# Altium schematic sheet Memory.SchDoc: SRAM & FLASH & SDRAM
size A4; DocumentNumber: MB1165; Revision: C.1; SheetNumber: 4; SheetTotal: 17; Project: STM32469I-EVAL
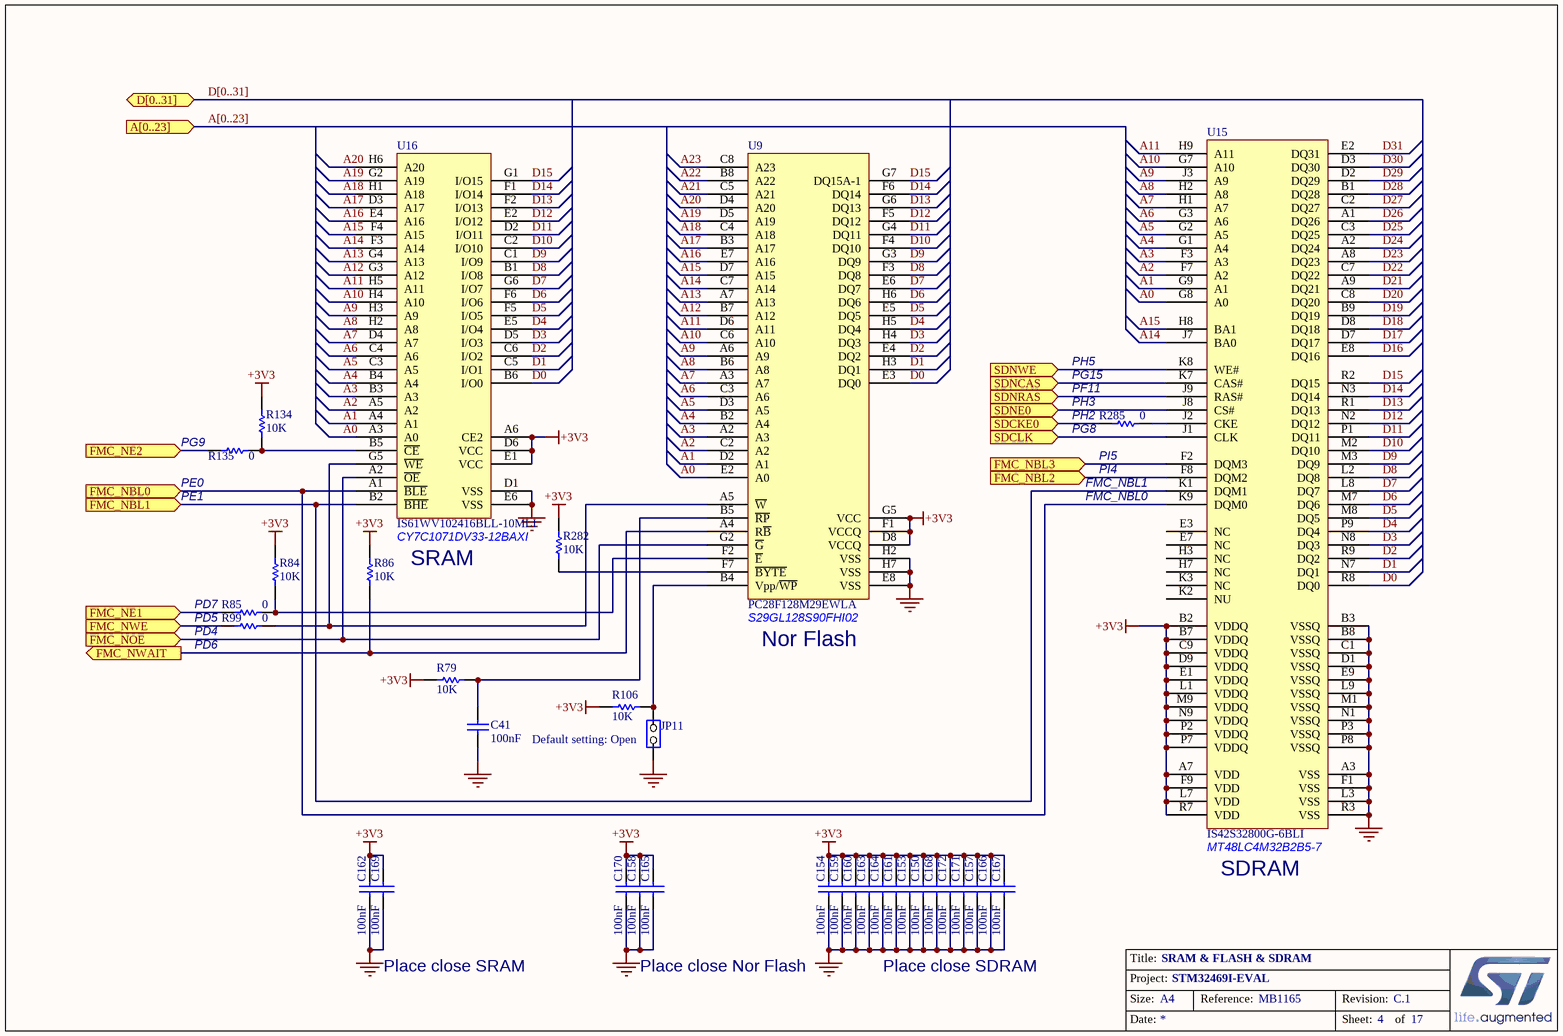
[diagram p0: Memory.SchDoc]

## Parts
C41  100nF  [0603C]
C150  100nF  [0603C]
C153  100nF  [0603C]
C154  100nF  [0603C]
C157  100nF  [0603C]
C158  100nF  [0603C]
C159  100nF  [0603C]
C160  100nF  [0603C]
C161  100nF  [0603C]
C162  100nF  [0603C]
C163  100nF  [0603C]
C164  100nF  [0603C]
C165  100nF  [0603C]
C166  100nF  [0603C]
C167  100nF  [0603C]
C168  100nF  [0603C]
C169  100nF  [0603C]
C170  100nF  [0603C]
C171  100nF  [0603C]
C172  100nF  [0603C]
JP11  (no value)  [SIP2]
R79  10K  [0603R]
R84  10K  [0603R]
R85  0  [0603R]
R86  10K  [0603R]
R99  0  [0603R]
R106  10K  [0603R]
R134  10K  [0603R]
R135  0  [0603R]
R282  10K  [0603R]
R285  0  [0603R]
U9  PC28F128M29EWLA  [FBGA64_1_11X13]
U15  IS42S32800G-6BLI  [FBGA90_0R8_8X13]
U16  IS61WV102416BLL-10MLI  [BGA48_0R75_9X11]

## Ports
A[0..23] (in), D[0..31] (bidir), FMC_NBL0 (in), FMC_NBL1 (in), FMC_NBL2 (in), FMC_NBL3 (in), FMC_NE1 (in), FMC_NE2 (in), FMC_NOE (in), FMC_NWAIT (out), FMC_NWE (in), SDCKE0 (in), SDCLK (in), SDNCAS (in), SDNE0 (in), SDNRAS (in), SDNWE (in)

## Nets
+3V3: C150.1 C153.1 C154.1 C157.1 C158.1 C159.1 C160.1 C161.1 C162.1 C163.1 C164.1 C165.1 C166.1 C167.1 C168.1 C169.1 C170.1 C171.1 C172.1 R79.1 R84.2 R86.2 R106.2 R134.2 R282.2 U9.D8(VCCQ) U9.F1(VCCQ) U9.G5(VCC) U15.A7(VDD) U15.B2(VDDQ) U15.B7(VDDQ) U15.C9(VDDQ) U15.D9(VDDQ) U15.E1(VDDQ) U15.F9(VDD) U15.L1(VDDQ) U15.L7(VDD) U15.M9(VDDQ) U15.N9(VDDQ) U15.P2(VDDQ) U15.P7(VDDQ) U15.R7(VDD) U16.A6(CE2) U16.D6(VCC) U16.E1(VCC)
GND: C41.2 C150.2 C153.2 C154.2 C157.2 C158.2 C159.2 C160.2 C161.2 C162.2 C163.2 C164.2 C165.2 C166.2 C167.2 C168.2 C169.2 C170.2 C171.2 C172.2 JP11.1(COMMON) U9.E8(VSS) U9.H2(VSS) U9.H7(VSS) U15.A3(VSS) U15.B3(VSSQ) U15.B8(VSSQ) U15.C1(VSSQ) U15.D1(VSSQ) U15.E9(VSSQ) U15.F1(VSS) U15.L3(VSS) U15.L9(VSSQ) U15.M1(VSSQ) U15.N1(VSSQ) U15.P3(VSSQ) U15.P8(VSSQ) U15.R3(VSS) U16.D1(VSS) U16.E6(VSS)
A0: U9.E2(A0) U15.G8(A0) U16.A3(A0)
A1: U9.D2(A1) U15.G9(A1) U16.A4(A1)
A2: U9.C2(A2) U15.F7(A2) U16.A5(A2)
A3: U9.A2(A3) U15.F3(A3) U16.B3(A3)
A4: U9.B2(A4) U15.G1(A4) U16.B4(A4)
A5: U9.D3(A5) U15.G2(A5) U16.C3(A5)
A6: U9.C3(A6) U15.G3(A6) U16.C4(A6)
A7: U9.A3(A7) U15.H1(A7) U16.D4(A7)
A8: U9.B6(A8) U15.H2(A8) U16.H2(A8)
A9: U9.A6(A9) U15.J3(A9) U16.H3(A9)
A10: U9.C6(A10) U15.G7(A10) U16.H4(A10)
A11: U9.D6(A11) U15.H9(A11) U16.H5(A11)
A12: U9.B7(A12) U16.G3(A12)
A13: U9.A7(A13) U16.G4(A13)
A14: U9.C7(A14) U15.J7(BA0) U16.F3(A14)
A15: U9.D7(A15) U15.H8(BA1) U16.F4(A15)
A16: U9.E7(A16) U16.E4(A16)
A17: U9.B3(A17) U16.D3(A17)
A18: U9.C4(A18) U16.H1(A18)
A19: U9.D5(A19) U16.G2(A19)
A20: U9.D4(A20) U16.H6(A20)
A21: U9.C5(A21)
A22: U9.B8(A22)
A23: U9.C8(A23)
D0: U9.E3(DQ0) U15.R8(DQ0) U16.B6(I/O0)
D1: U9.H3(DQ1) U15.N7(DQ1) U16.C5(I/O1)
D2: U9.E4(DQ2) U15.R9(DQ2) U16.C6(I/O2)
D3: U9.H4(DQ3) U15.N8(DQ3) U16.D5(I/O3)
D4: U9.H5(DQ4) U15.P9(DQ4) U16.E5(I/O4)
D5: U9.E5(DQ5) U15.M8(DQ5) U16.F5(I/O5)
D6: U9.H6(DQ6) U15.M7(DQ6) U16.F6(I/O6)
D7: U9.E6(DQ7) U15.L8(DQ7) U16.G6(I/O7)
D8: U9.F3(DQ8) U15.L2(DQ8) U16.B1(I/O8)
D9: U9.G3(DQ9) U15.M3(DQ9) U16.C1(I/O9)
D10: U9.F4(DQ10) U15.M2(DQ10) U16.C2(I/O10)
D11: U9.G4(DQ11) U15.P1(DQ11) U16.D2(I/O11)
D12: U9.F5(DQ12) U15.N2(DQ12) U16.E2(I/O12)
D13: U9.G6(DQ13) U15.R1(DQ13) U16.F2(I/O13)
D14: U9.F6(DQ14) U15.N3(DQ14) U16.F1(I/O14)
D15: U9.G7(DQ15A-1) U15.R2(DQ15) U16.G1(I/O15)
D16: U15.E8(DQ16)
D17: U15.D7(DQ17)
D18: U15.D8(DQ18)
D19: U15.B9(DQ19)
D20: U15.C8(DQ20)
D21: U15.A9(DQ21)
D22: U15.C7(DQ22)
D23: U15.A8(DQ23)
D24: U15.A2(DQ24)
D25: U15.C3(DQ25)
D26: U15.A1(DQ26)
D27: U15.C2(DQ27)
D28: U15.B1(DQ28)
D29: U15.D2(DQ29)
D30: U15.D3(DQ30)
D31: U15.E2(DQ31)
FMC_NBL0: U15.K9(DQM0) U16.A1(~{BLE}) ; port FMC_NBL0
FMC_NBL1: U15.K1(DQM1) U16.B2(~{BHE}) ; port FMC_NBL1
FMC_NBL2: U15.F8(DQM2) ; port FMC_NBL2
FMC_NBL3: U15.F2(DQM3) ; port FMC_NBL3
FMC_NE1: R85.2 ; port FMC_NE1
FMC_NE2: R135.2 ; port FMC_NE2
FMC_NOE: U9.G2(~{G}) U16.A2(~{OE}) ; port FMC_NOE
FMC_NWAIT: R86.1 U9.A4(R~{B}) ; port FMC_NWAIT
FMC_NWE: R99.2 ; port FMC_NWE
SDCKE0: R285.2 ; port SDCKE0
SDCLK: U15.J1(CLK) ; port SDCLK
SDNCAS: U15.K7(CAS#) ; port SDNCAS
SDNE0: U15.J8(CS#) ; port SDNE0
SDNRAS: U15.J9(RAS#) ; port SDNRAS
SDNWE: U15.K8(WE#) ; port SDNWE
NetC41_1: C41.1 R79.2 U9.B5(~{RP})
NetJP11_2: JP11.2(NO) R106.1 U9.B4(Vpp/~{WP})
NetR84_1: R84.1 R85.1 U9.F2(~{E})
NetR99_1: R99.1 U9.A5(~{W}) U16.G5(~{WE})
NetR134_1: R134.1 R135.1 U16.B5(~{CE})
NetR282_1: R282.1 U9.F7(~{BYTE})
NetR285_1: R285.1 U15.J2(CKE)

Not connected (* = marked no-connect by the designer): U15 E3(NC) E7(NC) H3(NC) H7(NC) K2(NU) K3(NC)

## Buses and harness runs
bus A[0..23] = port A[0..23]
bus D[0..31] = port D[0..31]

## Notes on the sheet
- PH5
- (near R285) PG15
- (near R135) PG9
- (near R285) PF11
- (near R285) PH3
- (near R285) PH2
- (near R285) PG8
- (near R135) PE1
- (near R135) PE0
- FMC_NBL1
- FMC_NBL0
- (near R285) PI5
- (near R285) PI4
- CY7C1071DV33-12BAXI
- SRAM
- PD5
- PD7
- PD6
- PD4
- (near U9) S29GL128S90FHI02
- (near U9) Nor Flash
- (near JP11) Default setting: Open
- (near U15) MT48LC4M32B2B5-7
- (near U15) SDRAM
- Place close SRAM
- Place close Nor Flash
- Place close SDRAM

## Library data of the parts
C41 C150 C153 C154 C157-C172 = Cap: Capacitor; Value: 10nF
JP11 = JP2
R79 R84-R86 R99 R106 R134 R135 R282 R285 = Res1: Resistor; Value: 1K
U9 = M29W128FL70ZA6E
U15 = MT48LC4M32B2B5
